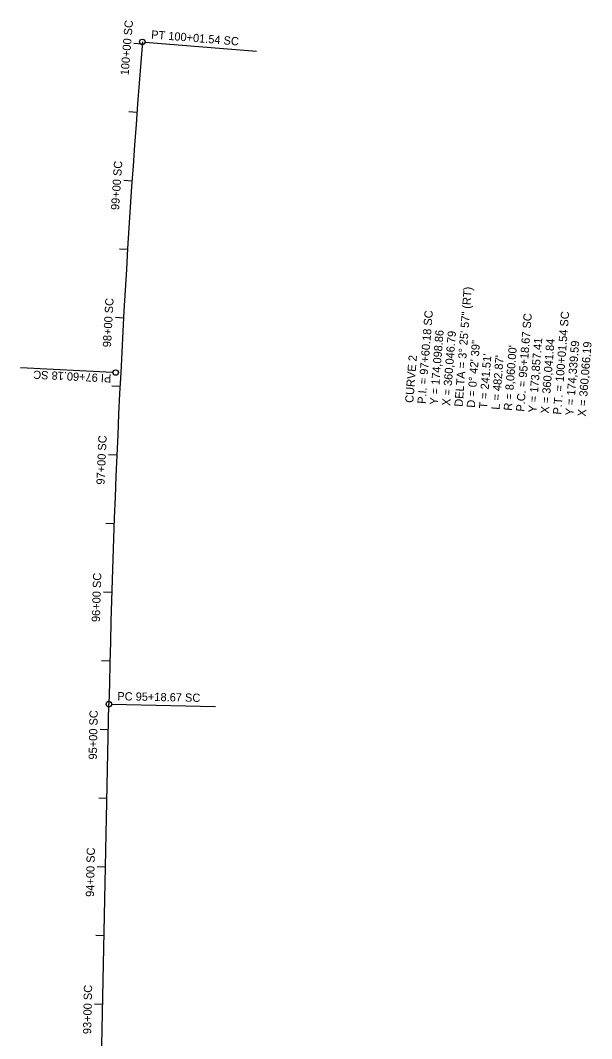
# Model space of a CAD drawing. Extents: x 356161 to 360393, y 172819 to 199204.
# Drawn here: x 359977 to 360393, y 173614 to 174355 of the extents above; entities that cross this region are included whole.
import ezdxf

# ---------------------------------------------------------------- set-up
doc = ezdxf.new("R2010")
doc.units = 0
for name, color, linetype in [('CA-MTCH-LINE', 7, 'Continuous'), ('CA-MTCH-LINE-TEXT', 7, 'Continuous'), ('Level 28', 7, 'Continuous'), ('P_PM_DotLane_50', 7, 'Continuous'), ('P_TC_Text', 7, 'Continuous')]:
    doc.layers.add(name, color=color, linetype=linetype)

msp = doc.modelspace()

# ---------------------------------------------------------------- linework, layer by layer
at = {"layer": 'CA-MTCH-LINE-TEXT'}
for p, q in [((360066.07, 174338.06), (360060.09, 174338.54)), ((360062.21, 174288.21), (360056.23, 174288.65)), ((360058.67, 174238.33), (360052.69, 174238.74)), ((360055.44, 174188.44), (360049.45, 174188.81)), ((360052.52, 174138.52), (360046.52, 174138.85)), ((360049.9, 174088.59), (360043.91, 174088.89)), ((360047.6, 174038.64), (360041.6, 174038.9)), ((360045.6, 173988.68), (360039.61, 173988.9)), ((360043.92, 173938.71), (360037.92, 173938.9)), ((360042.55, 173888.73), (360036.55, 173888.88)), ((360041.46, 173838.74), (360035.46, 173838.87)), ((360040.44, 173788.75), (360034.44, 173788.88)), ((360039.41, 173738.76), (360033.41, 173738.89)), ((360038.39, 173688.77), (360032.39, 173688.9)), ((360037.36, 173638.78), (360031.36, 173638.91))]:
    msp.add_line(p, q, dxfattribs=at)
at = {"layer": 'Level 28'}
for p, q in [((360068.18, 174339.43), (360149.37, 174332.89)), ((360044.79, 174098.96), (359977.38, 174102.37)), ((360043.84, 173857.37), (360119.56, 173855.81))]:
    msp.add_line(p, q, dxfattribs=at)
for centre in [(360066.19, 174339.59), (360046.79, 174098.86), (360041.84, 173857.41)]:
    msp.add_circle(centre, 2, dxfattribs=at)
at = {"layer": 'P_PM_DotLane_50'}
msp.add_line((360030.86, 173321.72), (360041.84, 173857.41), dxfattribs=at)
msp.add_arc((368100.15, 173692.23), 8060, 175.393179, 178.825735, dxfattribs=at)

# ---------------------------------------------------------------- texts
at = {"layer": 'CA-MTCH-LINE'}
for s, rotation, p in [('100+00 SC', 85.40412, (360056.19, 174315.04)), ('99+00 SC', 86.11498, (360049.21, 174217.03)), ('98+00 SC', 86.82585, (360043.32, 174117.15)), ('97+00 SC', 87.53672, (360038.67, 174017.16)), ('96+00 SC', 88.24758, (360035.26, 173917.12)), ('95+00 SC', 88.82573, (360033.01, 173817.06)), ('94+00 SC', 88.82573, (360030.96, 173717.08)), ('93+00 SC', 88.82573, (360028.92, 173617.1))]:
    msp.add_text(s, height=6, rotation=rotation, dxfattribs=at).set_placement(p)
at = {"layer": 'Level 28'}
for s, rotation, p in [('PT 100+01.54 SC', 355.39318, (360072.41, 174342.1)), ('PI 97+60.18 SC', 177.10946, (360043.72, 174097.52)), ('PC 95+18.67 SC', 358.82573, (360047.9, 173860.28))]:
    msp.add_text(s, height=6, rotation=rotation, dxfattribs=at).set_placement(p)
at = {"layer": 'P_TC_Text'}
for s, p in [('DELTA = 3%%d 25\' 57" (RT)', (360299.27, 174073.76)), ('P.I. = 97+60.18 SC', (360272.35, 174075.89)), ('P.C. = 95+18.67 SC', (360344.13, 174070.22)), ('P.T. = 100+01.54 SC', (360371.04, 174068.09)), ('Y = 174,098.86', (360281.32, 174075.18)), ('X = 360,046.79', (360290.3, 174074.47)), ('D = 0%%d 42\' 39"', (360308.24, 174073.05)), ("R = 8,060.00'", (360335.16, 174070.92)), ('Y = 173,857.41', (360353.1, 174069.51)), ('X = 360,041.84', (360362.07, 174068.8)), ('Y = 174,339.59', (360380.02, 174067.38)), ('X = 360,066.19', (360388.99, 174066.67)), ('CURVE 2', (360263.38, 174076.6)), ("T = 241.51'", (360317.21, 174072.34)), ("L = 482.87'", (360326.18, 174071.63))]:
    msp.add_text(s, height=6, rotation=85.476, dxfattribs=at).set_placement(p)

doc.saveas('drawing.dxf')
